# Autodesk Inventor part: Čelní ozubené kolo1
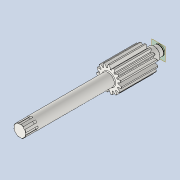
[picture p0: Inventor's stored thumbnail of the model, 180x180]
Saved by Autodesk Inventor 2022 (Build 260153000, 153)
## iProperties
CustomPartVersion: 1
Created: 2025-05
Part Number: Čelní ozubené kolo1
Material: Steel
Document SubType Name: Modeling
Designer: jbart
Categories: <?xml version="1.0" encoding="UTF-16"?> <MemberInstance><Categories><FamilyTemplate><FamilyTemplateParameter ValueType="xs:double" Id="1" ObjectReferenceKey="da
Density: 7.85 g/cm^3
Appearance: Steel
Mass: 13785.5 g
Surface Area: 1642.31 cm^2
Volume: 1756.11 cm^3
Author: jbart
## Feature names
1. Extrusion1
2. Vysunutí2 [Extrusion]
3. Vysunutí3 [Extrusion]
4. Vysunutí5 [Extrusion]
5. Zaoblení1 [Fillet]
6. Vysunutí6 [Extrusion]
7. Zkosení2 [Chamfer]
8. Zaoblení3 [Fillet]
9. Tažení1
10. Kruhové pole1 [Circular Pattern]
11. Zkosení3 [Chamfer]
## Parameters: d0 = 101.98908 mm, d2 = 0, d5 = 0, d16 = 261.61692 mm, d17 = 0, d34 = 12 deg, d39 = 0, da_righttooth = 0, da_lefttooth = 0, da_dw = 90.21273 mm, da_df = 75 mm, da_da = 101.98908 mm, da_beta = 0, da_aw = 261.61692 mm, d41 = 0, d43 = 261.61692 mm, d46 = 261.61692 mm, d47 = 0, d48 = 0, d50 = 35 mm, d51 = 0, d53 = 25 mm, d54 = 0, d55 = 18 mm, d56 = 37.5 mm, d59 = 1.85 mm, d60 = 0, d64 = 1 mm, d67 = 364 mm, d68 = 0, d69 = 1 mm, d70 = 2 mm, d71 = 45 deg, d72 = 3 mm, d74 = 23 mm, d76 = 9.289 mm, d77 = 4 mm, d78 = 23 mm, d79 = 0, d80 = 0, d82 = 360 deg, d84 = 1 mm, d85 = 2 mm, d86 = 45 deg
